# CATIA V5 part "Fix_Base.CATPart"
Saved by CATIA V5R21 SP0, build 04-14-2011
Part number: Fix_Base
Bounding box of the stored display mesh (mm): x -92.8 to 92.8, y -87.8 to 87.8, z 0 to 2.8
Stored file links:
  C:\Users\Pouria\Desktop\Box\Assembled\Fix_Base.CATPart
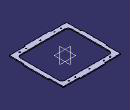
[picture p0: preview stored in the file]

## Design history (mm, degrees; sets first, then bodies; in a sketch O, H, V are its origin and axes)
Body1 (main body)
  Sketch1 on xy-plane, origin (0, 0, 0), H (1, 0, 0), V (0, 1, 0)
    line L1 (80, 70) -> (80, -70)
    line L2 (80, -70) -> (-80, -70)
    line L3 (-80, -70) -> (-80, 70)
    line L4 (-80, 70) -> (80, 70)
    line L5 (90, 85) -> (90, 40)
    line L6 (90, -85) -> (40, -85)
    line L7 (-90, -85) -> (-90, -40)
    line L8 (-90, 85) -> (-40, 85)
    line L9 (90, 40) -> (92.8, 40)
    line L10 (92.8, 40) -> (92.8, -40)
    line L11 (92.8, -40) -> (90, -40)
    point P12 (90, -40)
    point P13 (-90, 40)
    line L12 (-90, 40) -> (-92.8, 40)
    line L13 (-92.8, 40) -> (-92.8, -40)
    line L14 (-92.8, -40) -> (-90, -40)
    point P17 (40, 85)
    line L15 (40, 85) -> (40, 87.8)
    line L16 (40, 87.8) -> (-40, 87.8)
    line L17 (-40, 87.8) -> (-40, 85)
    line L18 (40, -85) -> (40, -87.8)
    line L19 (40, -87.8) -> (-40, -87.8)
    line L20 (-40, -87.8) -> (-40, -85)
    point P24 (-40, -85)
    line L21 (90, -40) -> (90, -85)
    line L22 (40, 85) -> (90, 85)
    line L23 (-90, 40) -> (-90, 85)
    line L24 (-40, -85) -> (-90, -85)
    circle A1 centre (0, 77.5) radius 1.9
    point P25 (0, 77.5)
    circle A2 centre (0, -77.5) radius 1.9
    point P26 (0, -77.5)
    circle A3 centre (65, 77.5) radius 1.9
    point P27 (65, 77.5)
    circle A4 centre (-65, 77.5) radius 1.9
    point P28 (-65, 77.5)
    circle A5 centre (-65, -77.5) radius 1.9
    point P29 (-65, -77.5)
    circle A6 centre (-45, -77.5) radius 1.5
    point P30 (-45, -77.5)
    circle A7 centre (45, -77.5) radius 1.5
    point P31 (45, -77.5)
    circle A8 centre (65, -77.5) radius 1.9
    point P32 (65, -77.5)
    circle A9 centre (45, 77.5) radius 1.5
    point P33 (45, 77.5)
    circle A10 centre (-45, 77.5) radius 1.5
    point P34 (-45, 77.5)
    distance L1 L5 = 10
    distance L2 L6 = 15
    distance L1 L3 = 160
    distance L4 L2 = 140
    length L11 = 2.8
    length L15 = 2.8
    length L10 = 80
    length L16 = 80
    distance P25 L4 = 7.5
    distance P33 L4 = 7.5
    distance P27 L4 = 7.5
    distance P34 L4 = 7.5
    distance P28 L4 = 7.5
    distance P29 L2 = 7.5
    distance P30 L2 = 7.5
    distance P26 L2 = 7.5
    distance P31 L2 = 7.5
    distance P32 L2 = 7.5
    distance P32 L21 = 25
    distance P29 L7 = 25
    distance P27 L5 = 25
    distance P28 L23 = 25
    radius A3 = 1.9
    radius A4 = 1.9
    radius A1 = 1.9
    radius A8 = 1.9
    radius A2 = 1.9
    radius A5 = 1.9
    distance P33 L5 = 45
    distance P34 L23 = 45
    distance P31 L21 = 45
    distance P30 L7 = 45
    radius A7 = 1.5
    radius A6 = 1.5
    radius A9 = 1.5
    radius A10 = 1.5
    vertical: L1 V, L3 V, L5 V, L7 V, L10 V, L13 V, L15 V, L17 V, L18 V, L20 V, L21 V, L23 V
    horizontal: L2 H, L4 H, L6 H, L8 H, L9 H, L11 H, L12 H, L14 H, L16 H, L19 H, L22 H, L24 H
    equidistance: L1 L3 O, L2 L4 O, L5 L7 O, L6 L8 O
    coincidence: P12 L5, P13 L7, P17 L8, P24 L6, L18 L15, L20 L17, L11 L14, L9 L12, L5 L21, L8 L22, L7 L23, L6 L24, P25 V, P26 V
    symmetry: L10 L13 V, L19 L16 H, L15 L17 V, L18 L20 V, L11 L9 H, L14 L12 H
  Pad1: profile Sketch1, direction (0, 0, 1), length 2.8
  Fillet1: radius 10, on edge [face of Pad1 from Sketch1.L4 | face of Pad1 from Sketch1.L3]; edge [face of Pad1 from Sketch1.L1 | face of Pad1 from Sketch1.L4]; edge [face of Pad1 from Sketch1.L2 | face of Pad1 from Sketch1.L1]; edge [face of Pad1 from Sketch1.L3 | face of Pad1 from Sketch1.L2]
